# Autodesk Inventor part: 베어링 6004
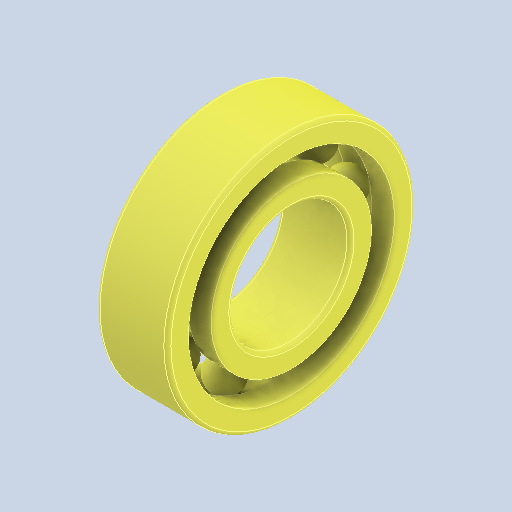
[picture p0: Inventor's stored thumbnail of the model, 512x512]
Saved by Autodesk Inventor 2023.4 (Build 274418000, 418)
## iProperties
Created: 2024-04
Part Number: 베어링 6004
Material: 강철, 연강
Description: 깊은 그루브 볼 베어링
Document SubType Name: Modeling
Designer: EDU
Density: 7.85 g/cm^3
Appearance: 기본값
Author: jhkim
Sending System: Autodesk Inventor 2025
Preprocessor: ST-DEVELOPER v20
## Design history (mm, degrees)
node "베어링 60041"
node "솔리드1"
node "솔리드2"
node "솔리드3"
node "솔리드4"
node "솔리드5"
node "솔리드6"
node "솔리드7"
node "솔리드8"
node "솔리드9"
node "솔리드10"
node "솔리드11"
body "Solid1"
node "Solid1:1"
node "Solid1:2"
node "Solid1:3"
node "Solid1:4"
node "Solid1:5"
node "Solid1:6"
node "Solid1:7"
node "Solid1:8"
node "Solid1:9"
node "Solid1:10"
